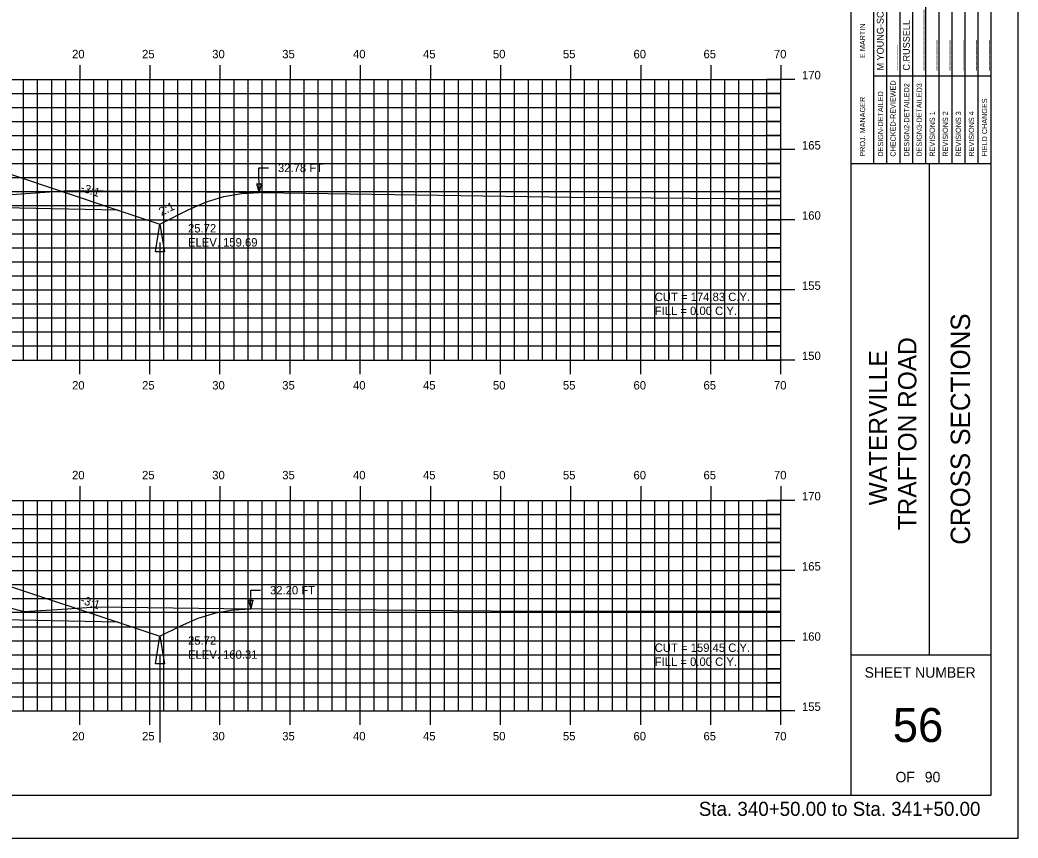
# Model space of a CAD drawing. Extents: x 1142976 to 1143146, y 608981 to 609091.
# Drawn here: x 1143075.3 to 1143146.5, y 608981.3 to 609039.6 of the extents above; entities that cross this region are included whole.
import ezdxf

# ---------------------------------------------------------------- set-up
doc = ezdxf.new("R2010")
doc.units = 0
for name, color, linetype in [('ANNOTATION', 7, 'Continuous'), ('BORDER', 7, 'Continuous'), ('D_Drainage_Ditch_Line', 7, 'Continuous'), ('D_Roadway_SlopeLines', 7, 'Continuous'), ('D_Roadway_SubGrade', 7, 'Continuous'), ('D_Text_Standard', 7, 'Continuous'), ('H_V ANNOTATION', 7, 'Continuous'), ('HIGHWAY_TITLE', 7, 'Continuous'), ('MAJOR', 7, 'Continuous'), ('MINOR', 7, 'Continuous'), ('PLOT BOUNDARY', 7, 'Continuous'), ('S_Roadway_Centerline', 7, 'Continuous')]:
    doc.layers.add(name, color=color, linetype=linetype)

msp = doc.modelspace()

# ---------------------------------------------------------------- linework, layer by layer
for points in [[(1143025.688, 609027.847), (1143026.938, 609027.77), (1143028.188, 609027.537), (1143029.438, 609027.147), (1143030.688, 609026.6), (1143033.842, 609025.023), (1143036.842, 609026.023), (1143044.566, 609028.598), (1143044.567, 609028.598), (1143048.567, 609028.758), (1143059.567, 609028.978), (1143070.567, 609028.758), (1143074.567, 609028.598), (1143082.29, 609026.023), (1143085.29, 609025.023), (1143087.35, 609026.053), (1143088.6, 609026.598), (1143089.85, 609026.983), (1143091.1, 609027.207), (1143092.35, 609027.271)], [(1143026.958, 608997.852), (1143028.208, 608997.769), (1143029.458, 608997.532), (1143030.708, 608997.139), (1143031.958, 608996.592), (1143033.842, 608995.649), (1143036.842, 608996.649), (1143044.566, 608999.224), (1143044.567, 608999.224), (1143048.567, 608999.384), (1143059.567, 608999.604), (1143070.567, 608999.384), (1143074.567, 608999.224), (1143082.29, 608996.65), (1143085.29, 608995.65), (1143086.768, 608996.388), (1143088.018, 608996.934), (1143089.268, 608997.32), (1143090.518, 608997.546), (1143091.768, 608997.614)]]:
    msp.add_lwpolyline(points)
at = {"layer": 'BORDER'}
for p, q in [((1143134.567, 608984.335), (1143134.567, 609089.335)), ((1143134.567, 609029.338), (1143144.567, 609029.338)), ((1143140.158, 608994.338), (1143140.158, 609029.338)), ((1143134.567, 608994.338), (1143144.567, 608994.338))]:
    msp.add_line(p, q, dxfattribs=at)
msp.add_lwpolyline([(1142984.567, 608984.335), (1143144.567, 608984.335), (1143144.567, 609089.335), (1142984.567, 609089.335)], close=True, dxfattribs=at)
for points in [[(1143137.114, 609029.341), (1143137.114, 609046.838)], [(1143138.046, 609046.838), (1143138.046, 609029.341)], [(1143138.978, 609029.341), (1143138.978, 609046.838)], [(1143139.909, 609029.341), (1143139.909, 609046.838)], [(1143140.841, 609029.341), (1143140.841, 609046.838)], [(1143141.773, 609029.341), (1143141.773, 609046.838)], [(1143142.704, 609029.341), (1143142.704, 609046.838)], [(1143143.636, 609029.341), (1143143.636, 609046.838)], [(1143136.182, 609029.341), (1143136.182, 609046.132)], [(1143136.182, 609035.588), (1143144.567, 609035.588)]]:
    msp.add_lwpolyline(points, dxfattribs=at)
at = {"layer": 'D_Drainage_Ditch_Line'}
for p, q in [((1143085.29, 609023.711), (1143085.29, 609017.468)), ((1143085.29, 608994.337), (1143085.29, 608988.094))]:
    msp.add_line(p, q, dxfattribs=at)
for points in [[(1143085.618, 609023.055), (1143084.962, 609023.055), (1143085.29, 609025.023)], [(1143085.618, 608993.681), (1143084.962, 608993.681), (1143085.29, 608995.65)]]:
    msp.add_lwpolyline(points, close=True, dxfattribs=at)
at = {"layer": 'D_Roadway_SlopeLines'}
for points in [[(1143085.29, 609025.023), (1143087.35, 609026.053), (1143088.6, 609026.598), (1143089.85, 609026.983), (1143091.1, 609027.207), (1143092.35, 609027.271)], [(1143082.29, 609026.023), (1143085.29, 609025.023)], [(1143085.29, 608995.65), (1143086.768, 608996.388), (1143088.018, 608996.934), (1143089.268, 608997.32), (1143090.518, 608997.546), (1143091.768, 608997.614)], [(1143082.29, 608996.65), (1143085.29, 608995.65)]]:
    msp.add_lwpolyline(points, dxfattribs=at)
at = {"layer": 'D_Roadway_SubGrade'}
for points in [[(1143070.567, 609028.341), (1143070.567, 609028.508), (1143074.567, 609028.348), (1143074.567, 609028.598), (1143074.567, 609028.598), (1143082.29, 609026.023), (1143070.567, 609026.258)], [(1143070.567, 608998.967), (1143070.567, 608999.134), (1143074.567, 608998.974), (1143074.567, 608999.224), (1143074.567, 608999.224), (1143082.29, 608996.65), (1143070.567, 608996.884)]]:
    msp.add_lwpolyline(points, close=True, dxfattribs=at)
at = {"layer": 'D_Text_Standard'}
for points in [[(1143092.35, 609027.303), (1143092.342, 609029.026), (1143093.022, 609029.026)], [(1143091.768, 608997.638), (1143091.775, 608998.935), (1143092.455, 608998.935)]]:
    msp.add_lwpolyline(points, dxfattribs=at)
for points in [[(1143092.35, 609027.303), (1143092.202, 609027.885), (1143092.493, 609027.886)], [(1143091.768, 608997.638), (1143091.625, 608998.221), (1143091.916, 608998.22)]]:
    msp.add_lwpolyline(points, close=True, dxfattribs=at)
at = {"layer": 'MAJOR'}
for p, q in [((1143079.567, 609036.337), (1143079.567, 609035.335)), ((1143084.567, 609036.337), (1143084.567, 609035.335)), ((1143089.567, 609036.337), (1143089.567, 609035.335)), ((1143094.567, 609036.337), (1143094.567, 609035.335)), ((1143099.567, 609036.337), (1143099.567, 609035.335)), ((1143104.567, 609036.337), (1143104.567, 609035.335)), ((1143109.567, 609036.337), (1143109.567, 609035.335)), ((1143114.567, 609036.337), (1143114.567, 609035.335)), ((1143119.567, 609036.337), (1143119.567, 609035.335)), ((1143124.567, 609036.337), (1143124.567, 609035.335)), ((1143129.567, 609036.337), (1143129.567, 609035.335)), ((1142989.567, 609035.335), (1143129.567, 609035.335)), ((1142989.567, 609035.335), (1143129.567, 609035.335)), ((1143079.567, 609015.335), (1143079.567, 609035.335)), ((1143084.567, 609015.335), (1143084.567, 609035.335)), ((1143089.567, 609015.335), (1143089.567, 609035.335)), ((1143094.567, 609015.335), (1143094.567, 609035.335)), ((1143099.567, 609015.335), (1143099.567, 609035.335)), ((1143104.567, 609015.335), (1143104.567, 609035.335)), ((1143109.567, 609015.335), (1143109.567, 609035.335)), ((1143114.567, 609015.335), (1143114.567, 609035.335)), ((1143119.567, 609015.335), (1143119.567, 609035.335)), ((1143124.567, 609015.335), (1143124.567, 609035.335)), ((1143130.569, 609035.335), (1143128.565, 609035.335)), ((1143129.567, 609015.335), (1143129.567, 609035.335)), ((1143129.567, 609015.335), (1143129.567, 609035.335)), ((1142989.567, 609030.335), (1143129.567, 609030.335)), ((1143130.569, 609030.335), (1143128.565, 609030.335)), ((1142989.567, 609025.335), (1143129.567, 609025.335)), ((1143130.569, 609025.335), (1143128.565, 609025.335)), ((1142989.567, 609020.335), (1143129.567, 609020.335)), ((1143130.569, 609020.335), (1143128.565, 609020.335)), ((1142989.567, 609015.335), (1143129.567, 609015.335)), ((1142989.567, 609015.335), (1143129.567, 609015.335)), ((1143079.567, 609014.333), (1143079.567, 609015.335)), ((1143084.567, 609014.333), (1143084.567, 609015.335)), ((1143089.567, 609014.333), (1143089.567, 609015.335)), ((1143094.567, 609014.333), (1143094.567, 609015.335)), ((1143099.567, 609014.333), (1143099.567, 609015.335)), ((1143104.567, 609014.333), (1143104.567, 609015.335)), ((1143109.567, 609014.333), (1143109.567, 609015.335)), ((1143114.567, 609014.333), (1143114.567, 609015.335)), ((1143119.567, 609014.333), (1143119.567, 609015.335)), ((1143124.567, 609014.333), (1143124.567, 609015.335)), ((1143130.569, 609015.335), (1143128.565, 609015.335)), ((1143129.567, 609014.333), (1143129.567, 609015.335)), ((1143079.567, 609006.337), (1143079.567, 609005.335)), ((1143084.567, 609006.337), (1143084.567, 609005.335)), ((1143089.567, 609006.337), (1143089.567, 609005.335)), ((1143094.567, 609006.337), (1143094.567, 609005.335)), ((1143099.567, 609006.337), (1143099.567, 609005.335)), ((1143104.567, 609006.337), (1143104.567, 609005.335)), ((1143109.567, 609006.337), (1143109.567, 609005.335)), ((1143114.567, 609006.337), (1143114.567, 609005.335)), ((1143119.567, 609006.337), (1143119.567, 609005.335)), ((1143124.567, 609006.337), (1143124.567, 609005.335)), ((1143129.567, 609006.337), (1143129.567, 609005.335)), ((1142989.567, 609005.335), (1143129.567, 609005.335)), ((1142989.567, 609005.335), (1143129.567, 609005.335)), ((1143079.567, 608990.335), (1143079.567, 609005.335)), ((1143084.567, 608990.335), (1143084.567, 609005.335)), ((1143089.567, 608990.335), (1143089.567, 609005.335)), ((1143094.567, 608990.335), (1143094.567, 609005.335)), ((1143099.567, 608990.335), (1143099.567, 609005.335)), ((1143104.567, 608990.335), (1143104.567, 609005.335)), ((1143109.567, 608990.335), (1143109.567, 609005.335)), ((1143114.567, 608990.335), (1143114.567, 609005.335)), ((1143119.567, 608990.335), (1143119.567, 609005.335)), ((1143124.567, 608990.335), (1143124.567, 609005.335)), ((1143130.569, 609005.335), (1143128.565, 609005.335)), ((1143129.567, 608990.335), (1143129.567, 609005.335)), ((1143129.567, 608990.335), (1143129.567, 609005.335)), ((1142989.567, 609000.335), (1143129.567, 609000.335)), ((1143130.569, 609000.335), (1143128.565, 609000.335)), ((1142989.567, 608995.335), (1143129.567, 608995.335)), ((1143130.569, 608995.335), (1143128.565, 608995.335)), ((1142989.567, 608990.335), (1143129.567, 608990.335)), ((1142989.567, 608990.335), (1143129.567, 608990.335)), ((1143079.567, 608989.333), (1143079.567, 608990.335)), ((1143084.567, 608989.333), (1143084.567, 608990.335)), ((1143089.567, 608989.333), (1143089.567, 608990.335)), ((1143094.567, 608989.333), (1143094.567, 608990.335)), ((1143099.567, 608989.333), (1143099.567, 608990.335)), ((1143104.567, 608989.333), (1143104.567, 608990.335)), ((1143109.567, 608989.333), (1143109.567, 608990.335)), ((1143114.567, 608989.333), (1143114.567, 608990.335)), ((1143119.567, 608989.333), (1143119.567, 608990.335)), ((1143124.567, 608989.333), (1143124.567, 608990.335)), ((1143130.569, 608990.335), (1143128.565, 608990.335)), ((1143129.567, 608989.333), (1143129.567, 608990.335))]:
    msp.add_line(p, q, dxfattribs=at)
at = {"layer": 'MINOR'}
for p, q in [((1143075.567, 609015.335), (1143075.567, 609035.335)), ((1143076.567, 609015.335), (1143076.567, 609035.335)), ((1143077.567, 609015.335), (1143077.567, 609035.335)), ((1143078.567, 609015.335), (1143078.567, 609035.335)), ((1143080.567, 609015.335), (1143080.567, 609035.335)), ((1143081.567, 609015.335), (1143081.567, 609035.335)), ((1143082.567, 609015.335), (1143082.567, 609035.335)), ((1143083.567, 609015.335), (1143083.567, 609035.335)), ((1143085.567, 609015.335), (1143085.567, 609035.335)), ((1143086.567, 609015.335), (1143086.567, 609035.335)), ((1143087.567, 609015.335), (1143087.567, 609035.335)), ((1143088.567, 609015.335), (1143088.567, 609035.335)), ((1143090.567, 609015.335), (1143090.567, 609035.335)), ((1143091.567, 609015.335), (1143091.567, 609035.335)), ((1143092.567, 609015.335), (1143092.567, 609035.335)), ((1143093.567, 609015.335), (1143093.567, 609035.335)), ((1143095.567, 609015.335), (1143095.567, 609035.335)), ((1143096.567, 609015.335), (1143096.567, 609035.335)), ((1143097.567, 609015.335), (1143097.567, 609035.335)), ((1143098.567, 609015.335), (1143098.567, 609035.335)), ((1143100.567, 609015.335), (1143100.567, 609035.335)), ((1143101.567, 609015.335), (1143101.567, 609035.335)), ((1143102.567, 609015.335), (1143102.567, 609035.335)), ((1143103.567, 609015.335), (1143103.567, 609035.335)), ((1143105.567, 609015.335), (1143105.567, 609035.335)), ((1143106.567, 609015.335), (1143106.567, 609035.335)), ((1143107.567, 609015.335), (1143107.567, 609035.335)), ((1143108.567, 609015.335), (1143108.567, 609035.335)), ((1143110.567, 609015.335), (1143110.567, 609035.335)), ((1143111.567, 609015.335), (1143111.567, 609035.335)), ((1143112.567, 609015.335), (1143112.567, 609035.335)), ((1143113.567, 609015.335), (1143113.567, 609035.335)), ((1143115.567, 609015.335), (1143115.567, 609035.335)), ((1143116.567, 609015.335), (1143116.567, 609035.335)), ((1143117.567, 609015.335), (1143117.567, 609035.335)), ((1143118.567, 609015.335), (1143118.567, 609035.335)), ((1143120.567, 609015.335), (1143120.567, 609035.335)), ((1143121.567, 609015.335), (1143121.567, 609035.335)), ((1143122.567, 609015.335), (1143122.567, 609035.335)), ((1143123.567, 609015.335), (1143123.567, 609035.335)), ((1143125.567, 609015.335), (1143125.567, 609035.335)), ((1143126.567, 609015.335), (1143126.567, 609035.335)), ((1143127.567, 609015.335), (1143127.567, 609035.335)), ((1143128.567, 609015.335), (1143128.567, 609035.335)), ((1142989.567, 609034.335), (1143129.567, 609034.335)), ((1143129.567, 609034.335), (1143128.565, 609034.335)), ((1142989.567, 609033.335), (1143129.567, 609033.335)), ((1143129.567, 609033.335), (1143128.565, 609033.335)), ((1142989.567, 609032.335), (1143129.567, 609032.335)), ((1143129.567, 609032.335), (1143128.565, 609032.335)), ((1142989.567, 609031.335), (1143129.567, 609031.335)), ((1143129.567, 609031.335), (1143128.565, 609031.335)), ((1142989.567, 609029.335), (1143129.567, 609029.335)), ((1143129.567, 609029.335), (1143128.565, 609029.335)), ((1142989.567, 609028.335), (1143129.567, 609028.335)), ((1143129.567, 609028.335), (1143128.565, 609028.335)), ((1142989.567, 609027.335), (1143129.567, 609027.335)), ((1143129.567, 609027.335), (1143128.565, 609027.335)), ((1142989.567, 609026.335), (1143129.567, 609026.335)), ((1143129.567, 609026.335), (1143128.565, 609026.335)), ((1142989.567, 609024.335), (1143129.567, 609024.335)), ((1143129.567, 609024.335), (1143128.565, 609024.335)), ((1142989.567, 609023.335), (1143129.567, 609023.335)), ((1143129.567, 609023.335), (1143128.565, 609023.335)), ((1142989.567, 609022.335), (1143129.567, 609022.335)), ((1143129.567, 609022.335), (1143128.565, 609022.335)), ((1142989.567, 609021.335), (1143129.567, 609021.335)), ((1143129.567, 609021.335), (1143128.565, 609021.335)), ((1142989.567, 609019.335), (1143129.567, 609019.335)), ((1143129.567, 609019.335), (1143128.565, 609019.335)), ((1142989.567, 609018.335), (1143129.567, 609018.335)), ((1143129.567, 609018.335), (1143128.565, 609018.335)), ((1142989.567, 609017.335), (1143129.567, 609017.335)), ((1143129.567, 609017.335), (1143128.565, 609017.335)), ((1142989.567, 609016.335), (1143129.567, 609016.335)), ((1143129.567, 609016.335), (1143128.565, 609016.335)), ((1143075.567, 608990.335), (1143075.567, 609005.335)), ((1143076.567, 608990.335), (1143076.567, 609005.335)), ((1143077.567, 608990.335), (1143077.567, 609005.335)), ((1143078.567, 608990.335), (1143078.567, 609005.335)), ((1143080.567, 608990.335), (1143080.567, 609005.335)), ((1143081.567, 608990.335), (1143081.567, 609005.335)), ((1143082.567, 608990.335), (1143082.567, 609005.335)), ((1143083.567, 608990.335), (1143083.567, 609005.335)), ((1143085.567, 608990.335), (1143085.567, 609005.335)), ((1143086.567, 608990.335), (1143086.567, 609005.335)), ((1143087.567, 608990.335), (1143087.567, 609005.335)), ((1143088.567, 608990.335), (1143088.567, 609005.335)), ((1143090.567, 608990.335), (1143090.567, 609005.335)), ((1143091.567, 608990.335), (1143091.567, 609005.335)), ((1143092.567, 608990.335), (1143092.567, 609005.335)), ((1143093.567, 608990.335), (1143093.567, 609005.335)), ((1143095.567, 608990.335), (1143095.567, 609005.335)), ((1143096.567, 608990.335), (1143096.567, 609005.335)), ((1143097.567, 608990.335), (1143097.567, 609005.335)), ((1143098.567, 608990.335), (1143098.567, 609005.335)), ((1143100.567, 608990.335), (1143100.567, 609005.335)), ((1143101.567, 608990.335), (1143101.567, 609005.335)), ((1143102.567, 608990.335), (1143102.567, 609005.335)), ((1143103.567, 608990.335), (1143103.567, 609005.335)), ((1143105.567, 608990.335), (1143105.567, 609005.335)), ((1143106.567, 608990.335), (1143106.567, 609005.335)), ((1143107.567, 608990.335), (1143107.567, 609005.335)), ((1143108.567, 608990.335), (1143108.567, 609005.335)), ((1143110.567, 608990.335), (1143110.567, 609005.335)), ((1143111.567, 608990.335), (1143111.567, 609005.335)), ((1143112.567, 608990.335), (1143112.567, 609005.335)), ((1143113.567, 608990.335), (1143113.567, 609005.335)), ((1143115.567, 608990.335), (1143115.567, 609005.335)), ((1143116.567, 608990.335), (1143116.567, 609005.335)), ((1143117.567, 608990.335), (1143117.567, 609005.335)), ((1143118.567, 608990.335), (1143118.567, 609005.335)), ((1143120.567, 608990.335), (1143120.567, 609005.335)), ((1143121.567, 608990.335), (1143121.567, 609005.335)), ((1143122.567, 608990.335), (1143122.567, 609005.335)), ((1143123.567, 608990.335), (1143123.567, 609005.335)), ((1143125.567, 608990.335), (1143125.567, 609005.335)), ((1143126.567, 608990.335), (1143126.567, 609005.335)), ((1143127.567, 608990.335), (1143127.567, 609005.335)), ((1143128.567, 608990.335), (1143128.567, 609005.335)), ((1142989.567, 609004.335), (1143129.567, 609004.335)), ((1143129.567, 609004.335), (1143128.565, 609004.335)), ((1142989.567, 609003.335), (1143129.567, 609003.335)), ((1143129.567, 609003.335), (1143128.565, 609003.335)), ((1142989.567, 609002.335), (1143129.567, 609002.335)), ((1143129.567, 609002.335), (1143128.565, 609002.335)), ((1142989.567, 609001.335), (1143129.567, 609001.335)), ((1143129.567, 609001.335), (1143128.565, 609001.335)), ((1142989.567, 608999.335), (1143129.567, 608999.335)), ((1143129.567, 608999.335), (1143128.565, 608999.335)), ((1142989.567, 608998.335), (1143129.567, 608998.335)), ((1143129.567, 608998.335), (1143128.565, 608998.335)), ((1143129.567, 608997.335), (1142989.567, 608997.335)), ((1143129.567, 608997.335), (1143128.565, 608997.335)), ((1142989.567, 608996.335), (1143129.567, 608996.335)), ((1143129.567, 608996.335), (1143128.565, 608996.335)), ((1142989.567, 608994.335), (1143129.567, 608994.335)), ((1143129.567, 608994.335), (1143128.565, 608994.335)), ((1142989.567, 608993.335), (1143129.567, 608993.335)), ((1143129.567, 608993.335), (1143128.565, 608993.335)), ((1142989.567, 608992.335), (1143129.567, 608992.335)), ((1143129.567, 608992.335), (1143128.565, 608992.335)), ((1142989.567, 608991.335), (1143129.567, 608991.335)), ((1143129.567, 608991.335), (1143128.565, 608991.335))]:
    msp.add_line(p, q, dxfattribs=at)
at = {"layer": 'PLOT BOUNDARY'}
msp.add_lwpolyline([(1142976.473, 608981.276), (1143146.473, 608981.276), (1143146.473, 609091.276), (1142976.473, 609091.276)], close=True, dxfattribs=at)
at = {"layer": 'S_Roadway_Centerline'}
for points in [[(1143074.732, 609027.136), (1143077.419, 609027.321), (1143078.814, 609027.411), (1143090.952, 609027.293), (1143114.639, 609026.93), (1143125.976, 609026.849), (1143129.567, 609026.837)], [(1142989.567, 608997.913), (1143015.23, 608997.899), (1143015.369, 608997.901), (1143015.581, 608997.899), (1143035.144, 608997.818), (1143036.675, 608997.612), (1143039.235, 608997.313), (1143040.24, 608997.57), (1143042.363, 608998.094), (1143044.738, 608998.247), (1143045.936, 608998.359), (1143049.94, 608998.493), (1143057.403, 608998.694), (1143064.179, 608998.728), (1143068.256, 608998.668), (1143069.663, 608998.56), (1143071.984, 608998.313), (1143074.42, 608997.723), (1143075.581, 608997.422), (1143077.949, 608997.561), (1143080.787, 608997.747), (1143089.847, 608997.631), (1143111.617, 608997.433), (1143129.567, 608997.446)]]:
    msp.add_lwpolyline(points, dxfattribs=at)

# ---------------------------------------------------------------- texts
at = {"layer": 'ANNOTATION'}
for s, rotation, p in [('-3:1', 341.56521, (1143079.578, 609027.381)), ('2:1', 26.56505, (1143085.393, 609025.593)), ('-3:1', 341.56521, (1143079.578, 608998.008))]:
    msp.add_text(s, height=0.6, rotation=rotation, dxfattribs=at).set_placement(p)
at = {"layer": 'BORDER'}
for s, height, p in [('M YOUNG-SCAGGS', 0.48455, (1143136.89, 609035.961)), ('____________', 0.48455, (1143139.647, 609035.961)), ('E MARTIN', 0.3727, (1143135.571, 609036.855)), ('C.RUSSELL', 0.4845, (1143138.753, 609035.961)), ('_____', 0.4845, (1143137.784, 609035.961)), ('______', 0.4845, (1143140.579, 609035.961)), ('______', 0.4845, (1143141.511, 609035.961)), ('______', 0.4845, (1143142.442, 609035.961)), ('______', 0.4845, (1143143.374, 609035.961)), ('______', 0.4845, (1143144.306, 609035.961)), ('CHECKED-REVIEWED', 0.37275, (1143137.748, 609029.826)), ('DESIGN3-DETAILED3', 0.37275, (1143139.611, 609029.826)), ('DESIGN-DETAILED', 0.37275, (1143136.853, 609029.826)), ('DESIGN2-DETAILED2', 0.37275, (1143138.717, 609029.826)), ('PROJ. MANAGER', 0.37275, (1143135.571, 609029.826)), ('FIELD CHANGES', 0.37275, (1143144.269, 609029.826)), ('REVISIONS 1', 0.37275, (1143140.543, 609029.826)), ('REVISIONS 2', 0.37275, (1143141.474, 609029.826)), ('REVISIONS 3', 0.37275, (1143142.406, 609029.826)), ('REVISIONS 4', 0.37275, (1143143.338, 609029.826)), ('CROSS SECTIONS', 1.37787, (1143143.051, 609002.172))]:
    msp.add_text(s, height=height, rotation=90, dxfattribs=at).set_placement(p)
for s, height, p in [('SHEET NUMBER', 0.74527, (1143135.532, 608992.701)), ('56', 2.4194, (1143137.542, 608988.118)), ('OF', 0.7453, (1143137.734, 608985.248)), ('90', 0.7453, (1143139.823, 608985.248))]:
    msp.add_text(s, height=height, dxfattribs=at).set_placement(p)
at = {"layer": 'D_Text_Standard'}
for s, p in [('32.78 FT', (1143093.702, 609028.726)), ('25.72', (1143087.29, 609024.423)), ('ELEV. 159.69', (1143087.29, 609023.421)), ('CUT = 174.83 C.Y.', (1143120.567, 609019.535)), ('FILL = 0.00 C.Y.', (1143120.567, 609018.539)), ('32.20 FT', (1143093.135, 608998.635)), ('25.72', (1143087.29, 608995.05)), ('CUT = 159.45 C.Y.', (1143120.567, 608994.535)), ('ELEV. 160.31', (1143087.29, 608994.048)), ('FILL = 0.00 C.Y.', (1143120.567, 608993.539))]:
    msp.add_text(s, height=0.6, dxfattribs=at).set_placement(p)
at = {"layer": 'H_V ANNOTATION'}
for s, height, p in [('20', 0.6, (1143079.021, 609036.835)), ('25', 0.6, (1143084.012, 609036.835)), ('30', 0.6, (1143089.015, 609036.835)), ('35', 0.6, (1143094.007, 609036.835)), ('40', 0.6, (1143099.053, 609036.835)), ('45', 0.6, (1143104.045, 609036.835)), ('50', 0.6, (1143109.031, 609036.835)), ('55', 0.6, (1143114.023, 609036.835)), ('60', 0.6, (1143119.053, 609036.835)), ('65', 0.6, (1143124.045, 609036.835)), ('70', 0.6, (1143129.069, 609036.835)), ('170', 0.6, (1143131.067, 609035.335)), ('165', 0.6, (1143131.067, 609030.335)), ('160', 0.6, (1143131.067, 609025.335)), ('155', 0.6, (1143131.067, 609020.335)), ('150', 0.6, (1143131.067, 609015.335)), ('20', 0.6, (1143079.021, 609013.235)), ('25', 0.6, (1143084.012, 609013.235)), ('30', 0.6, (1143089.015, 609013.235)), ('35', 0.6, (1143094.007, 609013.235)), ('40', 0.6, (1143099.053, 609013.235)), ('45', 0.6, (1143104.045, 609013.235)), ('50', 0.6, (1143109.031, 609013.235)), ('55', 0.6, (1143114.023, 609013.235)), ('60', 0.6, (1143119.053, 609013.235)), ('65', 0.6, (1143124.045, 609013.235)), ('70', 0.6, (1143129.069, 609013.235)), ('20', 0.6, (1143079.021, 609006.835)), ('25', 0.6, (1143084.012, 609006.835)), ('30', 0.6, (1143089.015, 609006.835)), ('35', 0.6, (1143094.007, 609006.835)), ('40', 0.6, (1143099.053, 609006.835)), ('45', 0.6, (1143104.045, 609006.835)), ('50', 0.6, (1143109.031, 609006.835)), ('55', 0.6, (1143114.023, 609006.835)), ('60', 0.6, (1143119.053, 609006.835)), ('65', 0.6, (1143124.045, 609006.835)), ('70', 0.6, (1143129.069, 609006.835)), ('170', 0.6, (1143131.067, 609005.335)), ('165', 0.6, (1143131.067, 609000.335)), ('160', 0.6, (1143131.067, 608995.335)), ('155', 0.6, (1143131.067, 608990.335)), ('20', 0.6, (1143079.021, 608988.235)), ('25', 0.6, (1143084.012, 608988.235)), ('30', 0.6, (1143089.015, 608988.235)), ('35', 0.6, (1143094.007, 608988.235)), ('40', 0.6, (1143099.053, 608988.235)), ('45', 0.6, (1143104.045, 608988.235)), ('50', 0.6, (1143109.031, 608988.235)), ('55', 0.6, (1143114.023, 608988.235)), ('60', 0.6, (1143119.053, 608988.235)), ('65', 0.6, (1143124.045, 608988.235)), ('70', 0.6, (1143129.069, 608988.235)), ('Sta. 340+50.00 to Sta. 341+50.00', 1.0002, (1143123.712, 608982.855))]:
    msp.add_text(s, height=height, dxfattribs=at).set_placement(p)
at = {"layer": 'HIGHWAY_TITLE'}
for s, height, p in [('TRAFTON ROAD', 1.30428, (1143139.226, 609003.201)), ('WATERVILLE', 1.3043, (1143137.139, 609004.98))]:
    msp.add_text(s, height=height, rotation=90, dxfattribs=at).set_placement(p)

doc.saveas('drawing.dxf')
